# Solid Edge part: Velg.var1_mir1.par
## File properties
Author: jaanm
Template: Ansi Inch Part.par
Last saved by: jaanm
Revision: 2
Application: Solid Edge
Accuracy: 0,990
Username: jaanm
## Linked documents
Velg.var1.par
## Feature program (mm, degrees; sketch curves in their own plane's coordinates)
part copy "CopiedPart_1"
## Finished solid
Body 1: solid body, 77 faces, 180 edges, 89 vertices.
  Faces by surface: cylinder 40, plane 24, torus 12, cone 1
  Edges by curve: circle 81, line 68, intersection 30, curve on surface 1
Bounding box of the edges (mm; curved faces can reach further): 200.000 x 250.000 x 250.000, from (-108.955, -125, -158.5) to (91.045, 125, 91.5).
Cylindrical faces by radius (mm): R6.5 x7, R10 x17, R15 x1, R44.8943 x9, R79.6098 x5, R105 x1
Conical faces (half-angle, radius in mm at the cone's reference point): 0 deg R79.6098 x1
Toroidal faces (ring radius, tube radius in mm): R56.1241 r23.4857 x3, R89.6098 r10 x5, R99.375 r25.625 x2, R102.3049 r23.9455 x1, R106.5839 r6 x1
Planar faces by outward normal: +x 2, +z 2, -x 12, oblique 8
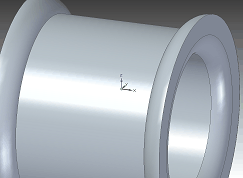
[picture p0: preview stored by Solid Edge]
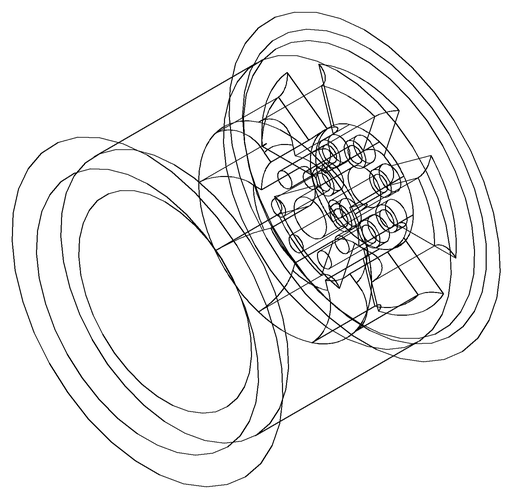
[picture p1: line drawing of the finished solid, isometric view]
